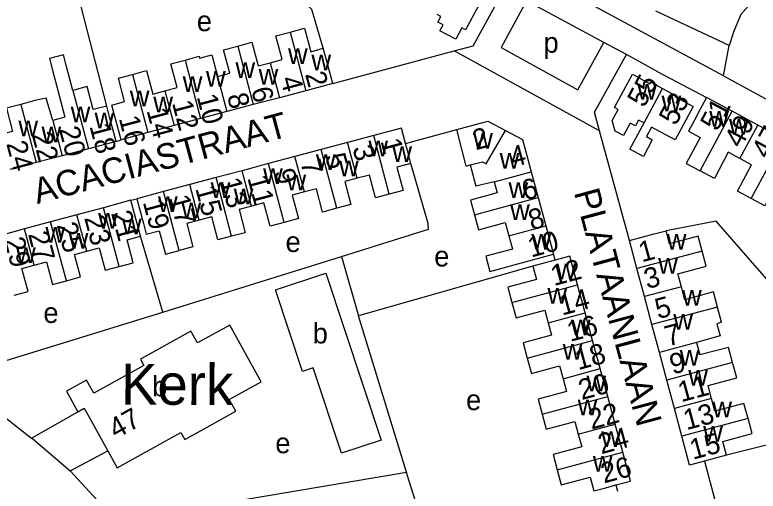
# Model space of a CAD drawing. Extents: x 159261 to 160849, y 382514 to 384534.
# Drawn here: x 159684.3 to 159830, y 383890.1 to 383983.5 of the extents above; entities that cross this region are included whole.
import ezdxf

# ---------------------------------------------------------------- set-up
doc = ezdxf.new("R2010")
doc.units = 0
for name, color, linetype in [('BLT_Basislijn', 7, 'Continuous'), ('BLT_Bebouwing', 7, 'Continuous'), ('BLT_Bebouwing_beschrifting', 7, 'Continuous'), ('BLT_Centroide', 7, 'Continuous'), ('BLT_Huisnummer', 7, 'Continuous'), ('BLT_Huisnummer_ tussenligend', 7, 'Continuous'), ('BLT_Onderverdeling_panden', 7, 'Continuous'), ('BLT_Straatnaam', 7, 'Continuous'), ('BLT_Vlakafsluiter', 7, 'Continuous')]:
    doc.layers.add(name, color=color, linetype=linetype)

msp = doc.modelspace()

# ---------------------------------------------------------------- linework, layer by layer
at = {"layer": 'BLT_Basislijn'}
for p, q in [((159702.28, 383965.63), (159695.15, 383993.41)), ((159784.62, 383986.25), (159779.62, 383977.11)), ((159799.77, 383978.1), (159784.62, 383986.25)), ((159794.65, 383968.85), (159799.77, 383978.1)), ((159804.19, 383975.76), (159799.77, 383978.1)), ((159746.59, 383970.05), (159770.41, 383976.46)), ((159798.91, 383960.8), (159770.41, 383976.46)), ((159779.62, 383977.11), (159794.65, 383968.85)), ((159797.92, 383964.44), (159804.19, 383975.76)), ((159810.33, 383972.37), (159804.19, 383975.76)), ((159810.33, 383972.37), (159819.88, 383967.29)), ((159798.91, 383960.8), (159797.92, 383964.44)), ((159760.88, 383958.27), (159770.93, 383961.02)), ((159804.76, 383939.25), (159798.91, 383960.8)), ((159704.12, 383958.7), (159705.09, 383959.04)), ((159707.02, 383947.16), (159708.18, 383947.47)), ((159713.32, 383925.22), (159708.92, 383940.11)), ((159713.32, 383925.22), (159748.3, 383936.14)), ((159748.3, 383936.14), (159751.63, 383924.49)), ((159790.22, 383935.42), (159789.9, 383936.57)), ((159785.85, 383934.24), (159751.63, 383924.49)), ((159672.21, 383912.53), (159713.32, 383925.22)), ((159761.07, 383893.82), (159751.63, 383924.49)), ((159687.55, 383900.54), (159696.61, 383905.69)), ((159858.86, 383906.11), (159823.8, 383897.17)), ((159695.11, 383894.1), (159702.49, 383898.01)), ((159819.47, 383896.01), (159823.59, 383880.46)), ((159722.68, 383887.36), (159761.07, 383893.82)), ((159802.11, 383891.33), (159802.43, 383890.09))]:
    msp.add_line(p, q, dxfattribs=at)
for points in [[(159823.19, 383971.58), (159776.17, 383997), (159741.85, 384015.38), (159709.1, 384032.76), (159673.65, 384051.74), (159650.3, 384064.56), (159643.13, 384067.61), (159637.08, 384069.2), (159632.59, 384069.5)], [(159744.75, 383976.96), (159742.51, 383984.55), (159739.81, 383987.4), (159724.4, 383989.41)], [(159770.41, 383976.46), (159774.12, 383977.46), (159780.2, 383988.59)], [(159829.93, 383987.41), (159829.08, 383986.38), (159826.6, 383983.61), (159825.23, 383980.34), (159824.33, 383977.48)], [(159824.33, 383977.48), (159810.51, 383984.01), (159809.96, 383984.24)], [(159823.19, 383971.58), (160049.97, 383848.1), (160067.5, 383838.6), (160083.66, 383829.43)], [(159748.3, 383936.14), (159765.37, 383941.5), (159765.34, 383942.63), (159761.92, 383954.36)], [(159844.68, 383916.88), (159821.76, 383943.08), (159811.97, 383941.18)], [(159672.21, 383912.53), (159687.55, 383900.54)], [(159687.55, 383900.54), (159687.74, 383900.43), (159695.11, 383894.1)], [(159695.11, 383894.1), (159701.15, 383887.55), (159705.89, 383879.57)], [(159765.34, 383880.25), (159761.28, 383893.15), (159761.07, 383893.82)]]:
    msp.add_lwpolyline(points, dxfattribs=at)
at = {"layer": 'BLT_Bebouwing'}
for p, q in [((159746.59, 383970.05), (159741.31, 383968.65)), ((159741.31, 383968.65), (159736.15, 383967.28)), ((159736.15, 383967.28), (159731.03, 383965.92)), ((159819.88, 383967.29), (159818.52, 383964.74)), ((159824.9, 383964.61), (159819.88, 383967.29)), ((159731.03, 383965.92), (159725.86, 383964.55)), ((159725.86, 383964.55), (159720.68, 383963.18)), ((159829.95, 383961.91), (159824.9, 383964.61)), ((159720.68, 383963.18), (159715.52, 383961.81)), ((159834.94, 383959.25), (159829.95, 383961.91)), ((159710.36, 383960.44), (159705.09, 383959.04)), ((159715.52, 383961.81), (159710.36, 383960.44)), ((159772.79, 383953.88), (159770.93, 383961.02)), ((159754.63, 383959.84), (159749.51, 383958.47)), ((159704.12, 383958.7), (159698.69, 383957.25)), ((159749.51, 383958.47), (159744.33, 383957.1)), ((159698.69, 383957.25), (159693.58, 383955.9)), ((159744.33, 383957.1), (159739.19, 383955.73)), ((159784.41, 383956.9), (159785.52, 383952.77)), ((159688.46, 383954.54), (159683.3, 383953.17)), ((159693.58, 383955.9), (159688.46, 383954.54)), ((159739.19, 383955.73), (159734.03, 383954.35)), ((159734.03, 383954.35), (159728.82, 383952.96)), ((159772.79, 383953.88), (159773.53, 383954.08)), ((159773.53, 383954.08), (159774.65, 383949.91)), ((159728.82, 383952.96), (159723.72, 383951.61)), ((159785.52, 383952.77), (159786.89, 383947.69)), ((159718.58, 383950.24), (159713.42, 383948.86)), ((159723.72, 383951.61), (159718.58, 383950.24)), ((159713.42, 383948.86), (159708.18, 383947.47)), ((159786.89, 383947.69), (159788.4, 383942.13)), ((159707.02, 383947.16), (159701.63, 383945.71)), ((159701.63, 383945.71), (159696.45, 383944.31)), ((159691.29, 383942.92), (159686.14, 383941.54)), ((159696.45, 383944.31), (159691.29, 383942.92)), ((159686.14, 383941.54), (159680.99, 383940.15)), ((159788.4, 383942.13), (159789.9, 383936.57)), ((159806.24, 383933.77), (159804.76, 383939.25)), ((159807.71, 383928.28), (159806.24, 383933.77)), ((159796.07, 383925.11), (159794.59, 383930.59)), ((159809.18, 383922.79), (159807.71, 383928.28)), ((159797.55, 383919.66), (159796.07, 383925.11)), ((159810.65, 383917.32), (159809.18, 383922.79)), ((159799.04, 383914.15), (159797.55, 383919.66)), ((159817.94, 383919.28), (159818.56, 383916.85)), ((159812.12, 383911.86), (159810.65, 383917.32)), ((159800.51, 383908.69), (159799.04, 383914.15)), ((159813.59, 383906.36), (159812.12, 383911.86)), ((159801.98, 383903.26), (159800.51, 383908.69)), ((159815.06, 383900.9), (159813.59, 383906.36)), ((159803.46, 383897.8), (159801.98, 383903.26))]:
    msp.add_line(p, q, dxfattribs=at)
for points in [[(159770.61, 383990.23), (159772.72, 383989.15), (159772.59, 383988.91), (159776.07, 383987.05), (159772.62, 383980.58), (159771.91, 383980.96), (159770.74, 383978.75), (159767.62, 383980.41), (159768.23, 383981.55), (159767.19, 383982.1), (159767.78, 383983.21), (159767.06, 383983.59)], [(159738.26, 383980.14), (159741.06, 383980.88), (159742.28, 383976.3), (159744.75, 383976.96)], [(159734.33, 383974.14), (159736.69, 383974.77), (159735.46, 383979.39), (159738.26, 383980.14)], [(159727.98, 383977.41), (159730.74, 383978.14), (159731.97, 383973.52), (159734.33, 383974.14)], [(159724.03, 383971.44), (159726.43, 383972.08), (159725.21, 383976.68), (159727.98, 383977.41)], [(159746.59, 383970.05), (159745.3, 383974.89), (159744.75, 383976.96)], [(159695.65, 383968.71), (159694.4, 383973.41), (159693.79, 383975.7), (159691.04, 383974.95), (159691.67, 383972.67), (159692.87, 383967.97), (159694.07, 383963.43), (159691.74, 383962.81)], [(159717.64, 383974.66), (159720.39, 383975.39), (159720.49, 383975.01), (159722.91, 383975.66), (159724.03, 383971.44)], [(159713.71, 383968.64), (159716.12, 383969.28), (159714.88, 383973.93), (159717.64, 383974.66)], [(159707.33, 383971.85), (159710.08, 383972.58), (159711.3, 383968), (159713.71, 383968.64)], [(159705.09, 383959.04), (159703.8, 383963.87), (159703.28, 383965.84), (159705.8, 383966.51), (159704.58, 383971.12), (159707.33, 383971.85)], [(159801.36, 383962.8), (159802.53, 383964.99), (159801.86, 383965.35), (159805.35, 383971.87)], [(159805.35, 383971.87), (159808.8, 383970.02), (159808.96, 383970.32), (159811.25, 383969.1)], [(159702.28, 383965.63), (159699.63, 383964.93), (159698.43, 383969.44), (159695.65, 383968.71)], [(159811.25, 383969.1), (159813.8, 383967.74), (159813.67, 383967.48), (159817.26, 383965.57)], [(159691.74, 383962.81), (159690.42, 383967.18), (159688.21, 383966.7), (159685.42, 383965.96)], [(159685.42, 383965.96), (159682.63, 383965.22), (159683.84, 383960.67), (159681.47, 383960.04)], [(159704.12, 383958.7), (159702.84, 383963.53), (159702.28, 383965.63)], [(159817.26, 383965.57), (159814.9, 383961.16), (159813.77, 383959.04), (159809.1, 383961.53), (159808.09, 383959.64), (159809.26, 383959.02), (159807.52, 383955.77), (159804.88, 383957.18), (159807.63, 383962.32)], [(159818.52, 383964.74), (159817.53, 383962.88), (159816.36, 383960.7), (159818.63, 383959.49), (159815.9, 383954.39), (159818.66, 383952.92)], [(159770.93, 383961.02), (159777, 383962.66), (159780.45, 383960.85)], [(159807.63, 383962.32), (159806.54, 383962.9), (159805.93, 383961.74), (159804.93, 383962.28), (159803.64, 383959.86), (159801.99, 383960.74), (159801.36, 383962.8)], [(159760.88, 383958.27), (159760.08, 383961.29), (159754.63, 383959.84)], [(159780.45, 383960.85), (159783.82, 383959.09), (159784.41, 383956.9)], [(159761.92, 383954.36), (159761.36, 383956.46), (159760.88, 383958.27)], [(159826.44, 383955.35), (159824.15, 383956.57), (159821.42, 383951.45), (159818.66, 383952.92)], [(159828.65, 383947.48), (159825.95, 383948.93), (159828.73, 383954.13), (159826.44, 383955.35)], [(159761.92, 383954.36), (159759.2, 383953.63), (159760.4, 383949.09), (159757.69, 383948.37)], [(159757.69, 383948.37), (159754.97, 383947.64), (159753.78, 383952.11), (159751.37, 383951.47)], [(159751.37, 383951.47), (159748.97, 383950.83), (159750.16, 383946.34), (159747.39, 383945.6)], [(159778.27, 383950.81), (159778.87, 383948.61), (159773.61, 383947.19), (159774.39, 383944.3)], [(159778.27, 383950.81), (159774.65, 383949.91)], [(159836.39, 383950.03), (159834.13, 383951.23), (159831.35, 383946.04), (159828.65, 383947.48)], [(159741.04, 383948.79), (159738.67, 383948.16), (159739.89, 383943.57), (159737.1, 383942.82)], [(159747.39, 383945.6), (159744.62, 383944.86), (159743.41, 383949.42), (159741.04, 383948.79)], [(159708.18, 383947.47), (159709.47, 383942.64), (159710.03, 383940.53), (159712.58, 383941.2), (159713.8, 383936.6), (159716.5, 383937.32)], [(159708.92, 383940.11), (159708.33, 383942.33), (159707.02, 383947.16)], [(159730.67, 383946), (159728.25, 383945.35), (159729.46, 383940.81), (159726.78, 383940.1)], [(159737.1, 383942.82), (159734.31, 383942.08), (159733.09, 383946.64), (159730.67, 383946)], [(159720.44, 383943.24), (159717.98, 383942.59), (159719.19, 383938.04), (159716.5, 383937.32)], [(159726.78, 383940.1), (159724.1, 383939.38), (159722.9, 383943.9), (159720.44, 383943.24)], [(159774.39, 383944.3), (159775.19, 383941.37), (159780.44, 383942.79), (159781.15, 383940.16)], [(159704.73, 383934.18), (159707.49, 383934.92), (159706.29, 383939.4), (159708.92, 383940.11)], [(159781.15, 383940.16), (159781.85, 383937.58), (159776.63, 383936.17), (159777.43, 383933.21), (159785.08, 383935.27), (159789.9, 383936.57)], [(159804.76, 383939.25), (159809.59, 383940.55), (159811.97, 383941.18)], [(159819.01, 383937.2), (159818.22, 383940.15), (159812.65, 383938.65), (159811.97, 383941.18)], [(159694.39, 383931.39), (159697.13, 383932.12), (159695.94, 383936.56), (159698.36, 383937.21)], [(159698.36, 383937.21), (159700.78, 383937.86), (159701.97, 383933.43), (159704.73, 383934.18)], [(159814.95, 383930.22), (159814.27, 383932.77), (159819.8, 383934.26), (159819.01, 383937.2)], [(159794.59, 383930.59), (159793.08, 383936.19), (159790.22, 383935.42)], [(159684.11, 383928.54), (159686.86, 383929.28), (159685.64, 383933.79), (159688.05, 383934.44)], [(159688.05, 383934.44), (159690.46, 383935.09), (159691.65, 383930.65), (159694.39, 383931.39)], [(159785.85, 383934.24), (159786.55, 383931.65), (159780.92, 383930.13), (159781.74, 383927.11)], [(159790.22, 383935.42), (159788.25, 383934.89), (159785.85, 383934.24)], [(159822.05, 383926.23), (159821.26, 383929.18), (159815.64, 383927.67), (159814.95, 383930.22)], [(159781.74, 383927.11), (159782.56, 383924.1), (159788.16, 383925.61), (159788.83, 383923.16)], [(159822.84, 383923.27), (159822.05, 383926.23)], [(159702.49, 383898.01), (159704.33, 383894.69), (159716.83, 383901.62), (159717.6, 383900.24), (159721.97, 383902.67), (159727.59, 383905.79), (159726.32, 383908.07), (159732.6, 383911.55), (159726.42, 383922.69), (159720.08, 383919.18), (159718.8, 383921.48), (159708.9, 383915.98), (159709.56, 383914.79), (159699.74, 383909.35), (159698.33, 383911.9), (159694.39, 383909.71), (159696.61, 383905.69)], [(159788.83, 383923.16), (159789.49, 383920.7), (159783.92, 383919.2), (159784.73, 383916.2)], [(159822.84, 383923.27), (159821.92, 383922.91), (159822.55, 383920.56), (159817.94, 383919.28)], [(159825.01, 383915.32), (159824.21, 383918.29), (159818.56, 383916.85)], [(159784.73, 383916.2), (159785.54, 383913.19), (159791.08, 383914.69), (159791.75, 383912.18)], [(159820.85, 383908.31), (159820.18, 383910.83), (159825.81, 383912.34), (159825.01, 383915.32)], [(159791.75, 383912.18), (159792.43, 383909.67), (159786.86, 383908.16), (159787.65, 383905.21)], [(159828.03, 383904.38), (159827.23, 383907.34), (159821.53, 383905.79), (159820.85, 383908.31)], [(159696.61, 383905.69), (159697.85, 383906.38), (159702.49, 383898.01)], [(159787.65, 383905.21), (159788.45, 383902.26), (159794.07, 383903.78), (159794.74, 383901.3)], [(159823.8, 383897.17), (159823.07, 383899.88), (159828.82, 383901.42), (159828.03, 383904.38)], [(159794.74, 383901.3), (159795.41, 383898.83), (159789.8, 383897.31), (159790.61, 383894.32)], [(159819.47, 383896.01), (159816.58, 383895.23), (159815.06, 383900.9)], [(159802.11, 383891.33), (159804.99, 383892.11), (159803.46, 383897.8)], [(159823.8, 383897.17), (159821.41, 383896.53), (159819.47, 383896.01)], [(159790.61, 383894.32), (159791.41, 383891.34), (159797.08, 383892.87), (159797.81, 383890.17), (159800.17, 383890.8), (159802.11, 383891.33)]]:
    msp.add_lwpolyline(points, dxfattribs=at)
msp.add_lwpolyline([(159756.07, 383900.15), (159748.29, 383897.58), (159742.76, 383914.31), (159740.66, 383913.61), (159735.37, 383929.58), (159745.24, 383932.85)], close=True, dxfattribs=at)
at = {"layer": 'BLT_Onderverdeling_panden'}
for p, q in [((159738.26, 383980.14), (159741.31, 383968.65)), ((159727.98, 383977.41), (159731.03, 383965.92)), ((159717.64, 383974.66), (159720.68, 383963.18)), ((159734.33, 383974.14), (159736.15, 383967.28)), ((159707.33, 383971.85), (159710.36, 383960.44)), ((159724.03, 383971.44), (159725.86, 383964.55)), ((159695.65, 383968.71), (159698.69, 383957.25)), ((159713.71, 383968.64), (159715.52, 383961.81)), ((159807.63, 383962.32), (159811.25, 383969.1)), ((159685.42, 383965.96), (159688.46, 383954.54)), ((159818.66, 383952.92), (159824.9, 383964.61)), ((159691.74, 383962.81), (159693.58, 383955.9)), ((159826.44, 383955.35), (159829.95, 383961.91)), ((159757.69, 383948.37), (159754.63, 383959.84)), ((159828.65, 383947.48), (159834.94, 383959.25)), ((159751.37, 383951.47), (159749.51, 383958.47)), ((159747.39, 383945.6), (159744.33, 383957.1)), ((159741.04, 383948.79), (159739.19, 383955.73)), ((159737.1, 383942.82), (159734.03, 383954.35)), ((159730.67, 383946), (159728.82, 383952.96)), ((159778.27, 383950.81), (159785.52, 383952.77)), ((159720.44, 383943.24), (159718.58, 383950.24)), ((159726.78, 383940.1), (159723.72, 383951.61)), ((159716.5, 383937.32), (159713.42, 383948.86)), ((159774.39, 383944.3), (159786.89, 383947.69)), ((159704.73, 383934.18), (159701.63, 383945.71)), ((159694.39, 383931.39), (159691.29, 383942.92)), ((159698.36, 383937.21), (159696.45, 383944.31)), ((159688.05, 383934.44), (159686.14, 383941.54)), ((159781.15, 383940.16), (159788.4, 383942.13)), ((159819.01, 383937.2), (159806.24, 383933.77)), ((159781.74, 383927.11), (159794.59, 383930.59)), ((159814.95, 383930.22), (159807.71, 383928.28)), ((159822.05, 383926.23), (159809.18, 383922.79)), ((159788.83, 383923.16), (159796.07, 383925.11)), ((159784.73, 383916.2), (159797.55, 383919.66)), ((159817.94, 383919.28), (159810.65, 383917.32)), ((159825.01, 383915.32), (159812.12, 383911.86)), ((159791.75, 383912.18), (159799.04, 383914.15)), ((159787.65, 383905.21), (159800.51, 383908.69)), ((159820.85, 383908.31), (159813.59, 383906.36)), ((159828.03, 383904.38), (159815.06, 383900.9)), ((159794.74, 383901.3), (159801.98, 383903.26)), ((159790.61, 383894.32), (159803.46, 383897.8))]:
    msp.add_line(p, q, dxfattribs=at)
msp.add_lwpolyline([(159773.53, 383954.08), (159775.94, 383954.73), (159776.69, 383954.3), (159780.45, 383960.85)], dxfattribs=at)
at = {"layer": 'BLT_Vlakafsluiter'}
msp.add_line((159823.19, 383971.58), (159824.33, 383977.48), dxfattribs=at)

# ---------------------------------------------------------------- texts
at = {"layer": 'BLT_Bebouwing_beschrifting'}
msp.add_text('Kerk', height=8, rotation=359.7607, dxfattribs=at).set_placement((159705.08, 383907.1))
at = {"layer": 'BLT_Centroide'}
for s, p in [('e', (159719.95, 383980.32)), ('p', (159787.92, 383976.1)), ('w', (159737.83, 383973.88)), ('w', (159742.42, 383972.64)), ('w', (159727.53, 383971.14)), ('w', (159721.75, 383969.41)), ('w', (159732.06, 383969.86)), ('w', (159717.19, 383968.39)), ('w', (159806.31, 383966.91)), ('w', (159706.81, 383965.61)), ('w', (159811.06, 383964.62)), ('w', (159711.42, 383964.38)), ('w', (159695.22, 383962.47)), ('w', (159699.89, 383961.28)), ('w', (159820.41, 383961.59)), ('w', (159684.97, 383959.73)), ('w', (159824.3, 383960)), ('w', (159689.5, 383958.52)), ('w', (159774.14, 383957.29)), ('w', (159753.59, 383955.81)), ('w', (159758.28, 383954.67)), ('w', (159743.3, 383953.09)), ('w', (159779.33, 383953.35)), ('w', (159747.84, 383951.88)), ('w', (159732.95, 383950.33)), ('w', (159737.53, 383949.11)), ('w', (159722.67, 383947.59)), ('w', (159781.06, 383947.62)), ('w', (159727.19, 383946.38)), ('w', (159712.34, 383944.84)), ('w', (159716.94, 383943.62)), ('w', (159781.38, 383943.28)), ('w', (159700.59, 383941.62)), ('w', (159705.27, 383940.5)), ('w', (159690.27, 383938.84)), ('w', (159694.83, 383937.69)), ('e', (159737.35, 383937.02)), ('w', (159785.55, 383937.47)), ('w', (159812.09, 383937.47)), ('w', (159684.52, 383934.88)), ('e', (159766.5, 383934.19)), ('w', (159810.4, 383932.75)), ('w', (159790.43, 383931.66)), ('w', (159788.7, 383926.88)), ('w', (159815.09, 383926.5)), ('e', (159689.87, 383923.11)), ('w', (159813.37, 383921.78)), ('b', (159742.67, 383919.08)), ('w', (159793.3, 383920.66)), ('w', (159791.68, 383915.91)), ('w', (159814.63, 383914.71)), ('w', (159816.3, 383910.84)), ('b', (159711.2, 383908.69)), ('w', (159796.34, 383909.69)), ('e', (159772.74, 383906.02)), ('w', (159794.62, 383905)), ('w', (159821.02, 383904.59)), ('w', (159819.23, 383899.81)), ('e', (159735.35, 383897.56)), ('w', (159799.23, 383898.78)), ('w', (159797.59, 383893.97))]:
    msp.add_text(s, height=4, dxfattribs=at).set_placement(p)
at = {"layer": 'BLT_Huisnummer'}
for s, rotation, p in [('2', 284.8607, (159741.16, 383971.89)), ('55', 61.8972, (159807.65, 383965.16)), ('8', 284.8578, (159725.85, 383967.65)), ('51', 61.8963, (159821.96, 383960.51)), ('14', 284.8602, (159710.08, 383964.76)), ('47', 61.8841, (159831.99, 383955.05)), ('20', 284.8732, (159692.89, 383961.13)), ('2', 15.1274, (159774.64, 383956.95)), ('1', 284.9131, (159755.93, 383958.79)), ('4', 15.1274, (159781.94, 383953.6)), ('7', 284.9169, (159740.22, 383954.62)), ('13', 284.9174, (159724.57, 383951.06)), ('6', 15.1274, (159784.28, 383947.06)), ('19', 285.0659, (159709.34, 383946.81)), ('25', 285.0725, (159692.44, 383942.31)), ('1', 15.022, (159807.19, 383934.97)), ('12', 15.1246, (159789.96, 383930.33)), ('5', 15.0253, (159810.39, 383923.83)), ('18', 15.1386, (159794.71, 383913.84)), ('9', 15.0191, (159813.26, 383912.97)), ('47', 29.0161, (159704.1, 383900.28)), ('15', 15.0075, (159817.2, 383896.27)), ('26', 15.1295, (159799.77, 383891.62))]:
    msp.add_text(s, height=4, rotation=rotation, dxfattribs=at).set_placement(p)
at = {"layer": 'BLT_Huisnummer_ tussenligend'}
for s, rotation, p in [('4', 284.8607, (159736.31, 383970.99)), ('6', 284.8607, (159730.56, 383968.87)), ('10', 284.8578, (159719.9, 383967.48)), ('53', 61.8963, (159813.84, 383961.61)), ('12', 284.8578, (159715.06, 383966.25)), ('16', 284.8602, (159704.63, 383963.24)), ('49', 61.8841, (159826.65, 383957.2)), ('18', 284.8602, (159698.88, 383961.72)), ('22', 284.8732, (159687.56, 383960.05)), ('24', 284.8732, (159682.57, 383958.28)), ('3', 284.9131, (159750.44, 383957.43)), ('5', 284.9131, (159745.06, 383955.86)), ('9', 284.9169, (159735.07, 383952.82)), ('11', 284.9169, (159729.84, 383951.55)), ('15', 284.9174, (159719.64, 383949.49)), ('17', 284.9174, (159714.49, 383947.71)), ('21', 285.0659, (159703.12, 383944.63)), ('8', 15.1274, (159785.57, 383941.26)), ('23', 285.0659, (159697.85, 383943.72)), ('29', 285.0725, (159682.13, 383939.4)), ('27', 285.0725, (159686.84, 383940.53)), ('10', 15.1274, (159785.48, 383935.91)), ('3', 15.022, (159808.25, 383929.72)), ('14', 15.1246, (159791.55, 383924.53)), ('16', 15.1246, (159793.16, 383919.38)), ('7', 15.0253, (159812.3, 383918.48)), ('20', 15.1386, (159795.39, 383907.96)), ('11', 15.0191, (159814.9, 383907.54)), ('22', 15.1386, (159797.33, 383902.17)), ('13', 15.0191, (159815.96, 383902.07)), ('24', 15.1386, (159799.25, 383897.34))]:
    msp.add_text(s, height=4, rotation=rotation, dxfattribs=at).set_placement(p)
at = {"layer": 'BLT_Straatnaam'}
for s, height, rotation, p in [('ACACIASTRAAT', 5, 15.0741, (159688.64, 383946.4)), ('PLATAANLAAN', 4.9999, 285.1244, (159793.87, 383948.74))]:
    msp.add_text(s, height=height, rotation=rotation, dxfattribs=at).set_placement(p)

doc.saveas('drawing.dxf')
